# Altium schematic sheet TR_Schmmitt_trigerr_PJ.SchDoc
size A4
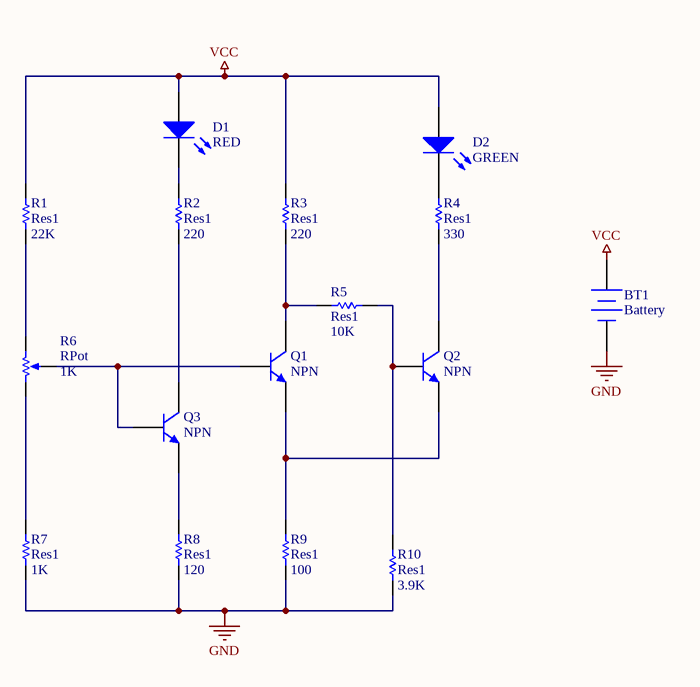
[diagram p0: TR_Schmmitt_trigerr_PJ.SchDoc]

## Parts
BT1  Battery  [BAT-2]
D1  RED  [3.2X1.6X1.1]
D2  GREEN  [3.2X1.6X1.1]
Q1  NPN  [npn]
Q2  NPN  [npn]
Q3  NPN  [npn]
R1  Res1  value 22K  [AXIAL-0.3]
R2  Res1  value 220  [AXIAL-0.3]
R3  Res1  value 220  [AXIAL-0.3]
R4  Res1  value 330  [AXIAL-0.3]
R5  Res1  value 10K  [AXIAL-0.3]
R6  RPot  value 1K  [RPOT_smd]
R7  Res1  value 1K  [AXIAL-0.3]
R8  Res1  value 120  [AXIAL-0.3]
R9  Res1  value 100  [AXIAL-0.3]
R10  Res1  value 3.9K  [AXIAL-0.3]

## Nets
GND: BT1.2(-) R7.1 R8.1 R9.1 R10.1
VCC: BT1.1(+) D1.1(A) D2.1(A) R1.2 R3.2
NetD1_2: D1.2(K) R2.2
NetD2_2: D2.2(K) R4.2
NetQ1_1: Q1.1(C) R3.1 R5.2
NetQ1_2: Q1.2(B) Q3.2(B) R6.3(TAP)
NetQ1_3: Q1.3(E) Q2.3(E) R9.2
NetQ2_1: Q2.1(C) R4.1
NetQ2_2: Q2.2(B) R5.1 R10.2
NetQ3_1: Q3.1(C) R2.1
NetQ3_3: Q3.3(E) R8.2
NetR1_1: R1.1 R6.1(TOP)
NetR6_2: R6.2(BOT) R7.2

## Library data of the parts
BT1 = Battery: Multicell Battery
D1 D2 = LED0: Typical INFRARED GaAs LED
Q1-Q3 = NPN: NPN Bipolar Transistor
R1-R5 R7-R10 = Res1: Resistor
R6 = RPot: Potentiometer; Sim Note: Enter the Resistance value and the set point into parameter fields.; Set Position: 0.5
